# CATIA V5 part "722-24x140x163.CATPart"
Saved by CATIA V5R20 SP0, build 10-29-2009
Part number: 722-24x140x163
Definition: NONE
Nomenclature: 722-24x140x163
Source: Unknown
Description: 722-24x140x163
Bounding box of the stored display mesh (mm): x -12 to 12, y -12 to 12, z -128 to 35
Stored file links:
  C:\Users\Utente\Desktop\IO LAVORO\3D X SITO CF\X SITO\722\722-24x140x163.CATPart
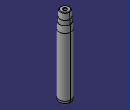
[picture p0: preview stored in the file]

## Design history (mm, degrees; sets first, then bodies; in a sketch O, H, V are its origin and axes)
Body1 "722-24x140x163" (main body)
  Solid1: solid without history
